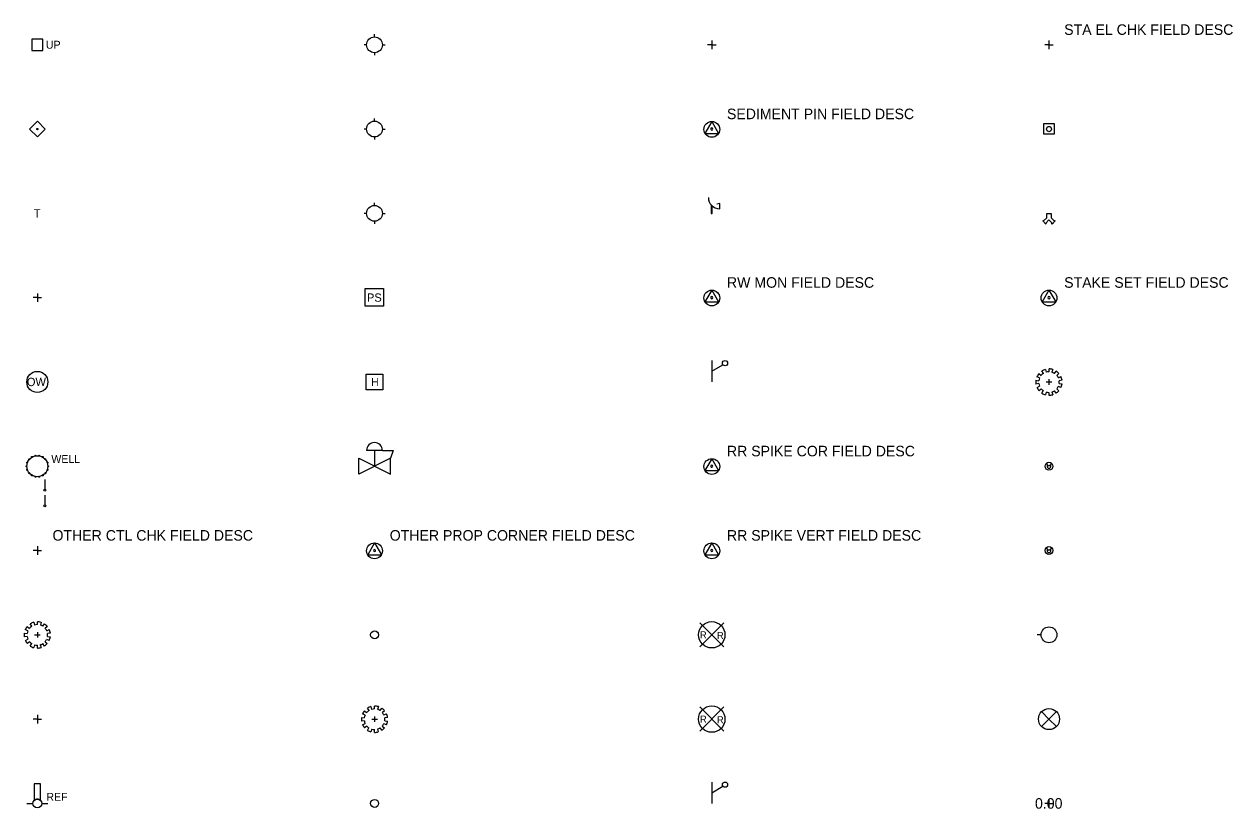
# Model space of a CAD drawing. Extents: x 91 to 2906, y -24 to 912.
# Drawn here: x 1492 to 2209, y 447 to 912 of the extents above; entities that cross this region are included whole.
import ezdxf

# ---------------------------------------------------------------- set-up
doc = ezdxf.new("R2010")
doc.units = 0
for name, color, linetype in [('B-BORE-HOLE', 7, 'Continuous'), ('B-WELL-PIZO', 7, 'Continuous'), ('V-CHAN-NAID', 7, 'Continuous'), ('V-COMM-EQPM', 7, 'Continuous'), ('V-CTRL-VERT', 7, 'Continuous'), ('V-FUEL-DEVC', 7, 'Continuous'), ('V-HTCW-DEVC', 7, 'Continuous'), ('V-HYDS-SOUN', 7, 'Continuous'), ('V-POWR-DEVC', 7, 'Continuous'), ('V-PRKG-FIXT', 7, 'Continuous'), ('V-PROP-LINE', 7, 'Continuous'), ('V-RAIL-EQPM', 7, 'Continuous'), ('V-SITE-OTLN', 7, 'Continuous'), ('V-SITE-VEGE', 7, 'Continuous'), ('V-SITE-WATR', 7, 'Continuous'), ('V-SSWR-DEVC', 7, 'Continuous'), ('V-STRM-STNS-PUMP', 7, 'Continuous'), ('V-SURV-DATA', 7, 'Continuous'), ('V-UTIL-DEVC', 7, 'Continuous'), ('V-WATR-DEVC', 7, 'Continuous'), ('V-WATR-VALT', 7, 'Continuous')]:
    doc.layers.add(name, color=color, linetype=linetype)

msp = doc.modelspace()

# ---------------------------------------------------------------- linework, layer by layer
at = {"layer": 'B-BORE-HOLE'}
for q in [(2095.57, 504.43), (2104.43, 504.43), (2095.57, 495.57), (2104.43, 495.57)]:
    msp.add_line((2100, 500), q, dxfattribs=at)
msp.add_circle((2100, 500), 6.25, dxfattribs=at)
at = {"layer": 'B-WELL-PIZO'}
for p, q in [((1700, 904.69), (1700, 906.25)), ((1695.31, 900), (1693.75, 900)), ((1704.69, 900), (1706.25, 900)), ((1700, 895.31), (1700, 893.75)), ((1700, 854.69), (1700, 856.25)), ((1695.31, 850), (1693.75, 850)), ((1704.69, 850), (1706.25, 850)), ((1700, 845.31), (1700, 843.75)), ((1700, 804.69), (1700, 806.25)), ((1695.31, 800), (1693.75, 800)), ((1704.69, 800), (1706.25, 800)), ((1700, 795.31), (1700, 793.75))]:
    msp.add_line(p, q, dxfattribs=at)
for centre in [(1700, 900), (1700, 850), (1700, 800)]:
    msp.add_circle(centre, 4.69, dxfattribs=at)
at = {"layer": 'V-CHAN-NAID'}
for p, q in [((1501.93, 461.6), (1498.07, 461.6)), ((1498.07, 461.6), (1498.07, 451.7)), ((1501.93, 451.7), (1501.93, 461.6)), ((1498.07, 451.7), (1498.07, 451.7)), ((1493.75, 450), (1497.42, 450)), ((1502.58, 450), (1506.25, 450))]:
    msp.add_line(p, q, dxfattribs=at)
msp.add_circle((1500, 450), 2.58, dxfattribs=at)
msp.add_arc((1500, 450), 2.58, 41.40795, 138.59088, dxfattribs=at)
at = {"layer": 'V-COMM-EQPM'}
for p, q in [((1499.97, 800.01), (1499.97, 800)), ((1499.97, 800), (1499.97, 799.99)), ((1499.98, 800.01), (1499.98, 800)), ((1499.98, 800), (1500, 800)), ((1499.98, 800), (1499.98, 799.99))]:
    msp.add_line(p, q, dxfattribs=at)
for points in [[(1899.72, 804.87), (1899.72, 800), (1900.28, 800), (1900.28, 804.32)], [(1904.69, 802.67), (1904.69, 805.81), (1903.02, 805.45)]]:
    msp.add_lwpolyline(points, dxfattribs=at)
msp.add_lwpolyline([(1499.97, 799.99), (1499.98, 799.99), (1499.98, 800.01), (1499.97, 800.01)], close=True, dxfattribs=at)
for centre, start, end in [((1904.69, 809.37), 180, 269.99971), ((1904.67, 809.39), 222.40921, 229.14002)]:
    msp.add_arc(centre, 6.71, start, end, dxfattribs=at)
at = {"layer": 'V-FUEL-DEVC'}
for p, q in [((1495.13, 654.09), (1495.13, 654.09)), ((1496.82, 655.5), (1496.82, 655.5)), ((1498.9, 656.25), (1498.9, 656.25)), ((1501.11, 656.25), (1501.11, 656.25)), ((1503.18, 655.5), (1503.18, 655.5)), ((1504.87, 654.09), (1504.87, 654.09)), ((1493.65, 650), (1493.65, 650)), ((1494.03, 652.18), (1494.03, 652.18)), ((1494.03, 647.82), (1494.03, 647.82)), ((1495.13, 645.91), (1495.13, 645.91)), ((1504.87, 645.91), (1504.87, 645.91)), ((1505.97, 652.18), (1505.97, 652.18)), ((1505.97, 647.82), (1505.97, 647.82)), ((1506.35, 650), (1506.35, 650)), ((1496.82, 644.5), (1496.82, 644.5)), ((1498.9, 643.75), (1498.9, 643.75)), ((1501.11, 643.75), (1501.11, 643.75)), ((1503.18, 644.5), (1503.18, 644.5)), ((1504.42, 642.06), (1504.42, 636.41)), ((1504.42, 632.76), (1504.42, 627.11))]:
    msp.add_line(p, q, dxfattribs=at)
for centre, radius in [((1494.03, 652.17), 0.282), ((1500, 650), 6.24), ((1495.14, 654.08), 0.282), ((1496.83, 655.5), 0.282), ((1498.9, 656.25), 0.282), ((1501.1, 656.25), 0.282), ((1503.18, 655.5), 0.282), ((1504.86, 654.08), 0.282), ((1505.97, 652.17), 0.282), ((1493.65, 650), 0.282), ((1494.03, 647.83), 0.282), ((1495.14, 645.92), 0.282), ((1504.86, 645.92), 0.282), ((1505.97, 647.83), 0.282), ((1506.35, 650), 0.282), ((1496.83, 644.5), 0.282), ((1498.9, 643.75), 0.282), ((1501.1, 643.75), 0.282), ((1503.18, 644.5), 0.282), ((1504.42, 635.85), 0.564), ((1504.42, 626.54), 0.564)]:
    msp.add_circle(centre, radius, dxfattribs=at)
at = {"layer": 'V-HTCW-DEVC'}
msp.add_lwpolyline([(2096.89, 847), (2096.89, 853.26), (2103.11, 853.26), (2103.11, 847)], close=True, dxfattribs=at)
msp.add_ellipse((2100, 850), major_axis=(0, 1.56), ratio=0.957579, dxfattribs=at)
at = {"layer": 'V-HYDS-SOUN'}
for p, q in [((2100, 452.55), (2100, 447.46)), ((2100, 450), (2097.46, 450)), ((2100, 450), (2102.55, 450))]:
    msp.add_line(p, q, dxfattribs=at)
at = {"layer": 'V-POWR-DEVC'}
msp.add_lwpolyline([(1695.11, 704.69), (1704.92, 704.69), (1704.92, 695.31), (1695.11, 695.31)], close=True, dxfattribs=at)
at = {"layer": 'V-PRKG-FIXT'}
for p, q in [((1500, 750), (1497.46, 750)), ((1500, 752.55), (1500, 747.46)), ((1500, 750), (1502.55, 750))]:
    msp.add_line(p, q, dxfattribs=at)
at = {"layer": 'V-PROP-LINE'}
msp.add_lwpolyline([(1500, 845.31), (1504.69, 850), (1500, 854.69), (1495.31, 850)], close=True, dxfattribs=at)
msp.add_circle((1500, 850), 0.391, dxfattribs=at)
at = {"layer": 'V-RAIL-EQPM'}
for p, q in [((1900, 712.68), (1900, 700)), ((1900.04, 706.35), (1906.54, 710.24)), ((1907.17, 542.81), (1892.82, 557.19)), ((1892.83, 542.81), (1907.18, 557.19)), ((1907.17, 492.81), (1892.82, 507.19)), ((1892.83, 492.81), (1907.18, 507.19)), ((1900, 462.68), (1900, 450)), ((1900.04, 456.35), (1906.54, 460.24))]:
    msp.add_line(p, q, dxfattribs=at)
for centre, radius in [((1907.87, 711.14), 1.55), ((1900, 550), 7.81), ((1900, 500), 7.81), ((1907.87, 461.14), 1.55)]:
    msp.add_circle(centre, radius, dxfattribs=at)
at = {"layer": 'V-SITE-OTLN'}
for p, q in [((2100, 650), (2098.34, 651.66)), ((2100, 650), (2101.66, 651.66)), ((2100, 600), (2098.34, 601.66)), ((2100, 600), (2101.66, 601.66)), ((1500, 502.55), (1500, 497.46)), ((1500, 500), (1497.46, 500)), ((1500, 500), (1502.55, 500))]:
    msp.add_line(p, q, dxfattribs=at)
for centre in [(2100, 650), (2100, 600), (1700, 550), (1700, 450)]:
    msp.add_circle(centre, 2.34, dxfattribs=at)
for centre in [(2100, 650), (2100, 600)]:
    msp.add_arc(centre, 1.17, 135, 45, dxfattribs=at)
at = {"layer": 'V-SITE-VEGE'}
for p, q in [((2094.41, 702.4), (2092.87, 703.08)), ((2094.04, 704.97), (2095.31, 703.84)), ((2096.74, 705.1), (2095.8, 706.51)), ((2097.86, 707.43), (2098.28, 705.79)), ((2100.02, 706.04), (2100.06, 707.73)), ((2102.25, 707.41), (2101.78, 705.78)), ((2103.3, 705.08), (2104.24, 706.47)), ((2105.93, 705.01), (2104.67, 703.9)), ((2105.59, 702.46), (2107.09, 703.21)), ((2092.25, 700.98), (2093.92, 700.7)), ((2093.94, 699.06), (2092.27, 698.76)), ((2092.89, 696.68), (2094.41, 697.43)), ((2095.4, 695.89), (2094.11, 694.78)), ((2098.35, 700), (2101.65, 700)), ((2100, 701.65), (2100, 698.35)), ((2104.6, 695.87), (2105.91, 694.78)), ((2107.11, 696.66), (2105.54, 697.3)), ((2106.06, 699), (2107.75, 698.8)), ((2107.75, 701), (2106.08, 700.73)), ((2095.82, 693.32), (2096.64, 694.78)), ((2098.35, 694.02), (2097.88, 692.41)), ((2100.02, 692.1), (2100.02, 693.79)), ((2101.69, 694.04), (2102.22, 692.43)), ((2104.24, 693.36), (2103.34, 694.78)), ((1494.41, 552.4), (1492.87, 553.08)), ((1494.04, 554.97), (1495.31, 553.84)), ((1496.74, 555.1), (1495.8, 556.51)), ((1497.86, 557.43), (1498.28, 555.79)), ((1500.02, 556.04), (1500.06, 557.73)), ((1502.25, 557.41), (1501.78, 555.78)), ((1503.3, 555.08), (1504.24, 556.47)), ((1505.93, 555.01), (1504.67, 553.9)), ((1505.59, 552.46), (1507.09, 553.21)), ((1492.25, 550.98), (1493.92, 550.7)), ((1493.94, 549.06), (1492.27, 548.76)), ((1492.89, 546.68), (1494.41, 547.43)), ((1495.4, 545.89), (1494.11, 544.78)), ((1498.35, 550), (1501.65, 550)), ((1500, 551.65), (1500, 548.35)), ((1504.6, 545.87), (1505.91, 544.78)), ((1507.11, 546.66), (1505.54, 547.3)), ((1506.06, 549), (1507.75, 548.8)), ((1507.75, 551), (1506.08, 550.73)), ((1495.82, 543.32), (1496.64, 544.78)), ((1498.35, 544.02), (1497.88, 542.41)), ((1500.02, 542.1), (1500.02, 543.79)), ((1501.69, 544.04), (1502.22, 542.43)), ((1504.24, 543.36), (1503.34, 544.78)), ((1694.41, 502.4), (1692.87, 503.08)), ((1694.04, 504.97), (1695.31, 503.84)), ((1696.74, 505.1), (1695.8, 506.51)), ((1697.86, 507.43), (1698.28, 505.79)), ((1700.02, 506.04), (1700.06, 507.73)), ((1702.25, 507.41), (1701.78, 505.78)), ((1703.3, 505.08), (1704.24, 506.47)), ((1705.93, 505.01), (1704.67, 503.9)), ((1705.59, 502.46), (1707.09, 503.21)), ((1692.25, 500.98), (1693.92, 500.7)), ((1693.94, 499.06), (1692.27, 498.76)), ((1692.89, 496.68), (1694.41, 497.43)), ((1695.4, 495.89), (1694.11, 494.78)), ((1695.82, 493.32), (1696.64, 494.78)), ((1698.35, 500), (1701.65, 500)), ((1700, 501.65), (1700, 498.35)), ((1704.24, 493.36), (1703.34, 494.78)), ((1704.6, 495.87), (1705.91, 494.78)), ((1707.11, 496.66), (1705.54, 497.3)), ((1706.06, 499), (1707.75, 498.8)), ((1707.75, 501), (1706.08, 500.73)), ((1698.35, 494.02), (1697.88, 492.41)), ((1700.02, 492.1), (1700.02, 493.79)), ((1701.69, 494.04), (1702.22, 492.43))]:
    msp.add_line(p, q, dxfattribs=at)
for centre, radius, start, end in [((2100, 699.92), 7.81, 139.77774, 156.07384), ((2100, 699.92), 6.12, 122.25403, 140.08604), ((2100, 699.92), 7.81, 105.97198, 122.5562), ((2100, 699.92), 6.12, 89.94612, 106.34731), ((2100, 699.92), 7.81, 73.29517, 89.57177), ((2100, 699.92), 6.12, 57.451, 73.08433), ((2100, 699.92), 7.81, 40.71222, 57.11658), ((2100, 699.92), 6.12, 24.45291, 40.47744), ((2100, 699.92), 7.81, 7.96706, 24.86254), ((2100, 699.92), 7.81, 172.27003, 188.58296), ((2100, 699.92), 7.81, 204.53942, 220.98516), ((2100, 699.92), 6.12, 156.05568, 172.75584), ((2100, 699.92), 6.12, 188.06191, 204.03317), ((2100, 699.92), 6.12, 221.20616, 236.77954), ((2100, 699.92), 6.12, 318.64322, 334.57953), ((2100, 699.92), 6.12, 351.54306, 7.6203), ((2100, 699.92), 7.81, 335.31226, 351.70421), ((2100, 699.92), 7.81, 237.61079, 254.19806), ((2100, 699.92), 6.12, 254.31, 270.04303), ((2100, 699.92), 7.81, 270.03559, 286.34199), ((2100, 699.92), 6.12, 285.95586, 303.05638), ((2100, 699.92), 7.81, 302.84338, 319.02216), ((1500, 549.92), 7.81, 139.77774, 156.07384), ((1500, 549.92), 6.12, 156.05568, 172.75584), ((1500, 549.92), 6.12, 122.25403, 140.08604), ((1500, 549.92), 7.81, 105.97198, 122.5562), ((1500, 549.92), 6.12, 89.94612, 106.34731), ((1500, 549.92), 7.81, 73.29517, 89.57177), ((1500, 549.92), 6.12, 57.451, 73.08433), ((1500, 549.92), 7.81, 40.71222, 57.11658), ((1500, 549.92), 6.12, 24.45291, 40.47744), ((1500, 549.92), 7.81, 7.96706, 24.86254), ((1500, 549.92), 7.81, 172.27003, 188.58296), ((1500, 549.92), 7.81, 204.53942, 220.98516), ((1500, 549.92), 6.12, 188.06191, 204.03317), ((1500, 549.92), 6.12, 221.20616, 236.77954), ((1500, 549.92), 6.12, 318.64322, 334.57953), ((1500, 549.92), 6.12, 351.54306, 7.6203), ((1500, 549.92), 7.81, 335.31226, 351.70421), ((1500, 549.92), 7.81, 237.61079, 254.19806), ((1500, 549.92), 6.12, 254.31, 270.04303), ((1500, 549.92), 7.81, 270.03559, 286.34199), ((1500, 549.92), 6.12, 285.95586, 303.05638), ((1500, 549.92), 7.81, 302.84338, 319.02216), ((1700, 499.92), 7.81, 139.77774, 156.07384), ((1700, 499.92), 6.12, 156.05568, 172.75584), ((1700, 499.92), 6.12, 122.25403, 140.08604), ((1700, 499.92), 7.81, 105.97198, 122.5562), ((1700, 499.92), 6.12, 89.94612, 106.34731), ((1700, 499.92), 7.81, 73.29517, 89.57177), ((1700, 499.92), 6.12, 57.451, 73.08433), ((1700, 499.92), 7.81, 40.71222, 57.11658), ((1700, 499.92), 6.12, 24.45291, 40.47744), ((1700, 499.92), 7.81, 7.96706, 24.86254), ((1700, 499.92), 7.81, 172.27003, 188.58296), ((1700, 499.92), 7.81, 204.53942, 220.98516), ((1700, 499.92), 6.12, 188.06191, 204.03317), ((1700, 499.92), 6.12, 221.20616, 236.77954), ((1700, 499.92), 6.12, 285.95586, 303.05638), ((1700, 499.92), 7.81, 302.84338, 319.02216), ((1700, 499.92), 6.12, 318.64322, 334.57953), ((1700, 499.92), 6.12, 351.54306, 7.6203), ((1700, 499.92), 7.81, 335.31226, 351.70421), ((1700, 499.92), 7.81, 237.61079, 254.19806), ((1700, 499.92), 6.12, 254.31, 270.04303), ((1700, 499.92), 7.81, 270.03559, 286.34199)]:
    msp.add_arc(centre, radius, start, end, dxfattribs=at)
at = {"layer": 'V-SITE-WATR'}
for p, q in [((1900, 900), (1897.46, 900)), ((1900, 902.55), (1900, 897.46)), ((1900, 900), (1902.55, 900))]:
    msp.add_line(p, q, dxfattribs=at)
at = {"layer": 'V-SSWR-DEVC'}
msp.add_circle((1500, 700), 6.25, dxfattribs=at)
at = {"layer": 'V-STRM-STNS-PUMP'}
msp.add_lwpolyline([(1694.42, 755.51), (1705.38, 755.51), (1705.38, 744.93), (1694.42, 744.93)], close=True, dxfattribs=at)
at = {"layer": 'V-SURV-DATA'}
for p, q in [((2100, 900), (2097.46, 900)), ((2100, 902.55), (2100, 897.46)), ((2100, 900), (2102.55, 900)), ((1900, 854.48), (1895.95, 847.46)), ((1900, 854.48), (1904.05, 847.46)), ((1895.95, 847.46), (1904.05, 847.46)), ((1900, 754.48), (1895.95, 747.46)), ((1900, 754.48), (1904.05, 747.46)), ((2100, 754.48), (2095.95, 747.46)), ((2100, 754.48), (2104.05, 747.46)), ((1895.95, 747.46), (1904.05, 747.46)), ((2095.95, 747.46), (2104.05, 747.46)), ((1900, 654.48), (1895.95, 647.46)), ((1900, 654.48), (1904.05, 647.46)), ((1895.95, 647.46), (1904.05, 647.46)), ((1500, 602.55), (1500, 597.46)), ((1700, 604.48), (1695.95, 597.46)), ((1700, 604.48), (1704.05, 597.46)), ((1900, 604.48), (1895.95, 597.46)), ((1900, 604.48), (1904.05, 597.46)), ((1500, 600), (1497.46, 600)), ((1500, 600), (1502.55, 600)), ((1695.95, 597.46), (1704.05, 597.46)), ((1895.95, 597.46), (1904.05, 597.46))]:
    msp.add_line(p, q, dxfattribs=at)
for centre in [(1900, 849.8), (1900, 749.8), (2100, 749.8), (1900, 649.8), (1700, 599.8), (1900, 599.8)]:
    msp.add_circle(centre, 4.69, dxfattribs=at)
for centre in [(1900, 850), (1900, 750), (2100, 750), (1900, 650), (1700, 600), (1900, 600)]:
    msp.add_arc(centre, 0.65, 92.28772, 90.56743, dxfattribs=at)
at = {"layer": 'V-UTIL-DEVC'}
msp.add_lwpolyline([(1496.67, 896.67), (1503.33, 896.67), (1503.33, 903.33), (1496.67, 903.33)], close=True, dxfattribs=at)
at = {"layer": 'V-WATR-DEVC'}
msp.add_line((2095.31, 550), (2092.97, 550), dxfattribs=at)
for points in [[(2100, 796.1), (2098.14, 794.24), (2098.42, 793.95), (2098.14, 793.67), (2096.27, 795.53), (2096.56, 795.82), (2096.84, 795.53), (2098.69, 797.38), (2098.69, 800), (2101.31, 800), (2101.31, 797.38)], [(2101.31, 797.38), (2103.16, 795.53), (2103.44, 795.82), (2103.73, 795.53), (2101.86, 793.67), (2101.58, 793.95), (2101.86, 794.24), (2100, 796.1)]]:
    msp.add_lwpolyline(points, dxfattribs=at)
msp.add_circle((2100, 550), 4.69, dxfattribs=at)
at = {"layer": 'V-WATR-VALT'}
msp.add_line((1700, 659.38), (1700, 650), dxfattribs=at)
msp.add_lwpolyline([(1690.62, 645.31), (1690.62, 654.69), (1709.38, 645.31), (1709.38, 654.69)], close=True, dxfattribs=at)
for points in [[(1704.69, 659.38), (1695.31, 659.38)], [(1704.69, 659.38), (1710.94, 659.38), (1709.38, 654.69)]]:
    msp.add_lwpolyline(points, dxfattribs=at)
msp.add_arc((1700, 659.38), 4.69, 0, 180, dxfattribs=at)

# ---------------------------------------------------------------- texts
at = {"layer": 'V-CHAN-NAID'}
msp.add_text('REF', height=4.687, dxfattribs=at).set_placement((1505.38, 451.55))
msp.add_text('REF', height=4.687, dxfattribs=at).set_placement((1505.38, 451.55))
at = {"layer": 'V-COMM-EQPM'}
msp.add_text('T', height=4.92, dxfattribs=at).set_placement((1497.95, 797.54))
at = {"layer": 'V-CTRL-VERT'}
msp.add_text('RR SPIKE VERT FIELD DESC', height=6.252, dxfattribs=at).set_placement((1909, 605.87))
at = {"layer": 'V-FUEL-DEVC'}
msp.add_text('WELL', height=4.68, dxfattribs=at).set_placement((1508.31, 651.93))
at = {"layer": 'V-HYDS-SOUN'}
msp.add_text('0.00', height=6.252, dxfattribs=at).set_placement((2091.71, 446.87))
at = {"layer": 'V-POWR-DEVC'}
msp.add_text('H', height=4.69, dxfattribs=at).set_placement((1697.92, 697.65))
at = {"layer": 'V-RAIL-EQPM'}
for p in [(1892.99, 547.91), (1903.05, 547.57), (1892.99, 497.91), (1903.05, 497.57)]:
    msp.add_text('R', height=4.13, dxfattribs=at).set_placement(p)
at = {"layer": 'V-SSWR-DEVC'}
msp.add_text('OW', height=4.921, dxfattribs=at).set_placement((1493.78, 697.54))
at = {"layer": 'V-STRM-STNS-PUMP'}
msp.add_text('PS', height=4.921, dxfattribs=at).set_placement((1695.49, 747.58))
at = {"layer": 'V-SURV-DATA'}
for s, p in [('STA EL CHK FIELD DESC', (2109, 905.87)), ('SEDIMENT PIN FIELD DESC', (1909, 855.87)), ('RW MON FIELD DESC', (1909, 755.87)), ('STAKE SET FIELD DESC', (2109, 755.87)), ('RR SPIKE COR FIELD DESC', (1909, 655.87)), ('OTHER CTL CHK FIELD DESC', (1509, 605.87)), ('OTHER PROP CORNER FIELD DESC', (1709, 605.87))]:
    msp.add_text(s, height=6.252, dxfattribs=at).set_placement(p)
at = {"layer": 'V-UTIL-DEVC'}
msp.add_text('UP', height=4.687, dxfattribs=at).set_placement((1505.1, 897.66))

doc.saveas('drawing.dxf')
